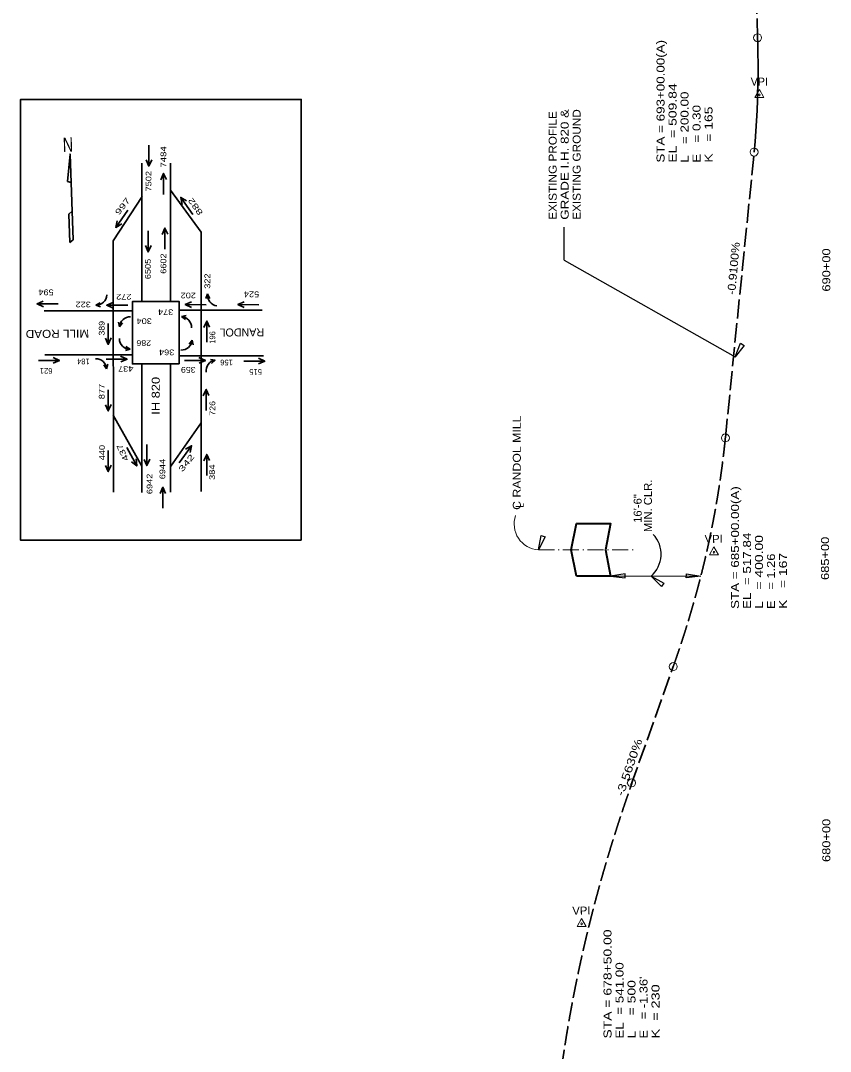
# Model space of a CAD drawing. Extents: x 2363427 to 2368559, y 6957299 to 6980140.
# Drawn here: x 2365431 to 2366849, y 6968482 to 6970286 of the extents above; entities that cross this region are included whole.
import ezdxf
from ezdxf.enums import TextEntityAlignment as Align

# ---------------------------------------------------------------- set-up
doc = ezdxf.new("R2010")
doc.units = 0
doc.header["$LTSCALE"] = 5.6
doc.linetypes.add('DOT_DASHED', pattern=[7.7, 5, -1.2, 0.3, -1.2])
doc.linetypes.add('LONG_DASHED', pattern=[7.5, 6, -1.5])
for name, color, linetype, lineweight in [('44', 7, 'Continuous', 13), ('45', 7, 'Continuous', 35), ('55', 7, 'Continuous', 35), ('61', 7, 'Continuous', 25)]:
    doc.layers.add(name, color=color, linetype=linetype, lineweight=lineweight)

msp = doc.modelspace()

# ---------------------------------------------------------------- linework, layer by layer
at = {"layer": '44'}
for p, q in [((2366724.404, 6970164.955), (2366716.366, 6970150.939)), ((2366724.404, 6970164.955), (2366732.527, 6970150.989)), ((2366716.366, 6970150.939), (2366732.527, 6970150.989)), ((2366644.717, 6969364.918), (2366636.98, 6969350.735)), ((2366636.98, 6969350.735), (2366653.136, 6969351.128)), ((2366644.717, 6969364.918), (2366653.136, 6969351.128)), ((2366413.104, 6968714.886), (2366405.367, 6968700.703)), ((2366405.367, 6968700.703), (2366421.523, 6968701.096)), ((2366413.104, 6968714.886), (2366421.523, 6968701.096))]:
    msp.add_line(p, q, dxfattribs=at)
at = {"layer": '44', "linetype": 'LONG_DASHED', "lineweight": 35}
for p, q in [((2366664.922, 6969555.558), (2366715.321, 6970055.621)), ((2366499.608, 6968947.727), (2366573.66, 6969155.558))]:
    msp.add_line(p, q, dxfattribs=at)
msp.add_lwpolyline([(2366715.321, 6970055.621), (2366716.875, 6970073.804), (2366718.23, 6970091.987), (2366719.384, 6970110.17), (2366720.339, 6970128.353), (2366721.094, 6970146.536), (2366721.396, 6970155.626), (2366721.851, 6970173.81), (2366722.105, 6970191.992), (2366722.16, 6970210.176), (2366722.014, 6970228.359), (2366721.669, 6970246.543), (2366721.421, 6970255.63), (2366697.42, 6971055.666)], dxfattribs=at)
at = {"layer": '44'}
for centre, radius in [((2366721.421, 6970255.63), 7), ((2366724.422, 6970155.625), 1.5), ((2366715.321, 6970055.621), 7), ((2366664.922, 6969555.558), 7), ((2366644.935, 6969355.59), 1.5), ((2366573.66, 6969155.558), 7), ((2366500.851, 6968952.141), 7), ((2366413.322, 6968705.558), 1.5)]:
    msp.add_circle(centre, radius, dxfattribs=at)
at = {"layer": '44', "linetype": 'LONG_DASHED', "lineweight": 35}
for points in [[(2366573.66, 6969155.558), (2366576.49, 6969163.558), (2366579.28, 6969171.558), (2366582.028, 6969179.558), (2366584.734, 6969187.558), (2366587.4, 6969195.558), (2366590.026, 6969203.558), (2366592.608, 6969211.558), (2366595.152, 6969219.558), (2366597.654, 6969227.558), (2366600.114, 6969235.558), (2366602.534, 6969243.558), (2366604.914, 6969251.558), (2366607.252, 6969259.558), (2366609.548, 6969267.558), (2366611.804, 6969275.558), (2366614.018, 6969283.558), (2366616.192, 6969291.558), (2366618.326, 6969299.558), (2366620.418, 6969307.558), (2366622.468, 6969315.558), (2366624.478, 6969323.558), (2366626.446, 6969331.558), (2366628.374, 6969339.558), (2366630.26, 6969347.558), (2366632.106, 6969355.558), (2366633.912, 6969363.558), (2366635.676, 6969371.558), (2366637.398, 6969379.558), (2366639.08, 6969387.558), (2366640.72, 6969395.558), (2366642.32, 6969403.558), (2366643.878, 6969411.558), (2366645.396, 6969419.558), (2366646.872, 6969427.558), (2366648.308, 6969435.558), (2366649.704, 6969443.558), (2366651.056, 6969451.558), (2366652.37, 6969459.558), (2366653.64, 6969467.558), (2366654.872, 6969475.558), (2366656.062, 6969483.558), (2366657.21, 6969491.558), (2366658.318, 6969499.558), (2366659.384, 6969507.558), (2366660.41, 6969515.558), (2366661.394, 6969523.558), (2366662.338, 6969531.558), (2366663.24, 6969539.558), (2366664.102, 6969547.558), (2366664.922, 6969555.558)], [(2366378.033, 6968452.021), (2366379.437, 6968462.021), (2366380.886, 6968472.021), (2366382.378, 6968482.022), (2366383.914, 6968492.022), (2366385.493, 6968502.023), (2366387.115, 6968512.023), (2366388.782, 6968522.023), (2366390.492, 6968532.024), (2366392.245, 6968542.024), (2366394.042, 6968552.025), (2366395.882, 6968562.025), (2366397.767, 6968572.026), (2366399.694, 6968582.026), (2366401.665, 6968592.027), (2366403.68, 6968602.027), (2366405.738, 6968612.028), (2366407.839, 6968622.028), (2366409.985, 6968632.029), (2366412.173, 6968642.03), (2366414.406, 6968652.03), (2366416.682, 6968662.031), (2366419.001, 6968672.031), (2366421.364, 6968682.032), (2366423.771, 6968692.033), (2366426.22, 6968702.033), (2366428.714, 6968712.034), (2366431.251, 6968722.035), (2366433.833, 6968732.035), (2366436.456, 6968742.036), (2366439.124, 6968752.037), (2366441.836, 6968762.037), (2366444.59, 6968772.038), (2366447.388, 6968782.039), (2366450.231, 6968792.04), (2366453.116, 6968802.04), (2366456.046, 6968812.041), (2366459.018, 6968822.042), (2366462.034, 6968832.043), (2366465.094, 6968842.043), (2366468.197, 6968852.044), (2366471.343, 6968862.045), (2366474.534, 6968872.046), (2366477.768, 6968882.047), (2366481.046, 6968892.048), (2366484.366, 6968902.049), (2366487.73, 6968912.049), (2366491.139, 6968922.05), (2366494.59, 6968932.051), (2366498.085, 6968942.052), (2366501.624, 6968952.053)]]:
    msp.add_spline(points, degree=3, dxfattribs=at)
at = {"layer": '45'}
msp.add_line((2365517.13, 6969897.208), (2365523.073, 6969902.238), dxfattribs=at)
for points in [[(2365523.073, 6969902.238), (2365517.838, 6970052.154), (2365513.392, 6970004.253), (2365519.583, 6970002.183)], [(2365517.13, 6969897.208), (2365515.385, 6969947.179), (2365521.328, 6969952.21)]]:
    msp.add_lwpolyline(points, dxfattribs=at)
at = {"layer": '55'}
for p, q in [((2365643.428, 6969794.124), (2365643.428, 6970035.87)), ((2365655.533, 6970031.053), (2365660.707, 6970042.25)), ((2365693.735, 6969794.124), (2365693.735, 6970035.87)), ((2365681.603, 6970018.34), (2365676.428, 6970007.144)), ((2365593.101, 6969900.17), (2365643.931, 6969978.073)), ((2365711.482, 6969976.179), (2365713.84, 6969964.072)), ((2365597.851, 6969923.779), (2365608.486, 6969930.032)), ((2365683.969, 6969922.663), (2365678.794, 6969911.467)), ((2365593.101, 6969900.17), (2365593.624, 6969460.907)), ((2365654.35, 6969881.039), (2365659.524, 6969892.236)), ((2365758.57, 6969807.362), (2365755.287, 6969799.598)), ((2365758.57, 6969807.362), (2365762.351, 6969799.405)), ((2365460.092, 6969789.861), (2365471.315, 6969784.736)), ((2365562.938, 6969787.591), (2365570.493, 6969792.125)), ((2365562.938, 6969787.591), (2365570.986, 6969785.078)), ((2365581.912, 6969787.499), (2365593.134, 6969782.374)), ((2365719.34, 6969788.908), (2365730.447, 6969783.539)), ((2365811.592, 6969788.908), (2365822.7, 6969783.539)), ((2365472.386, 6969778.042), (2365626.827, 6969778.042)), ((2365709.33, 6969779.047), (2365854.212, 6969779.047)), ((2365712.706, 6969767.821), (2365720.916, 6969769.744)), ((2365712.706, 6969767.821), (2365719.912, 6969762.751)), ((2365604.479, 6969749.622), (2365602.506, 6969757.818)), ((2365604.479, 6969749.622), (2365609.507, 6969756.857)), ((2365757.246, 6969759.972), (2365752.033, 6969748.793)), ((2365584.57, 6969719.215), (2365589.744, 6969730.411)), ((2365731.418, 6969726.786), (2365726.29, 6969719.62)), ((2365731.418, 6969726.786), (2365733.278, 6969718.564)), ((2365622.765, 6969710.643), (2365614.645, 6969708.367)), ((2365622.765, 6969710.643), (2365615.345, 6969715.398)), ((2365473.895, 6969700.643), (2365626.827, 6969700.643)), ((2365499.252, 6969690.814), (2365488.051, 6969695.987)), ((2365617.523, 6969693.176), (2365606.323, 6969698.349)), ((2365709.833, 6969699.135), (2365856.224, 6969699.135)), ((2365754.647, 6969690.942), (2365743.473, 6969696.172)), ((2365771.875, 6969691.567), (2365763.516, 6969692.675)), ((2365771.875, 6969691.567), (2365765.201, 6969685.813)), ((2365858.725, 6969689.761), (2365847.552, 6969694.991)), ((2365581.764, 6969676.243), (2365576.736, 6969683.478)), ((2365581.764, 6969676.243), (2365583.737, 6969684.439)), ((2365643.428, 6969459.902), (2365643.428, 6969685.062)), ((2365693.735, 6969460.907), (2365693.735, 6969685.062)), ((2365756.115, 6969640.355), (2365750.939, 6969629.159)), ((2365584.584, 6969602.859), (2365589.758, 6969614.055)), ((2365593.121, 6969595.098), (2365643.428, 6969506.14)), ((2365694.238, 6969506.14), (2365747.059, 6969582.032)), ((2365730.484, 6969541.819), (2365719.701, 6969535.829)), ((2365634.612, 6969506.485), (2365633.771, 6969518.791)), ((2365651.984, 6969507.197), (2365657.158, 6969518.394)), ((2365757.121, 6969526.77), (2365751.945, 6969515.574)), ((2365584.57, 6969496.568), (2365589.744, 6969507.764)), ((2365680.421, 6969469.355), (2365675.246, 6969458.158))]:
    msp.add_line(p, q, dxfattribs=at)
for points in [[(2365655.533, 6970067.766), (2365655.533, 6970031.053), (2365650.809, 6970041.862)], [(2365681.603, 6969981.628), (2365681.603, 6970018.34), (2365686.326, 6970007.533)], [(2365747.562, 6969461.912), (2365747.562, 6969915.249), (2365693.735, 6969988.928)], [(2365732.974, 6969946.409), (2365711.482, 6969976.179), (2365721.639, 6969970.178)], [(2365618.777, 6969953.949), (2365597.851, 6969923.779), (2365600.13, 6969935.352)], [(2365654.35, 6969917.752), (2365654.35, 6969881.039), (2365649.626, 6969891.848)], [(2365683.969, 6969885.95), (2365683.969, 6969922.663), (2365688.693, 6969911.856)], [(2365496.815, 6969790.02), (2365460.092, 6969789.861), (2365470.883, 6969794.63)], [(2365618.634, 6969787.658), (2365581.912, 6969787.499), (2365592.702, 6969792.268)], [(2365756.058, 6969788.262), (2365719.34, 6969788.908), (2365730.232, 6969793.44)], [(2365848.31, 6969788.262), (2365811.592, 6969788.908), (2365822.485, 6969793.44)], [(2365584.57, 6969755.928), (2365584.57, 6969719.215), (2365579.846, 6969730.023)], [(2365757.121, 6969723.259), (2365757.246, 6969759.972), (2365761.933, 6969749.147)], [(2365462.528, 6969690.814), (2365499.252, 6969690.814), (2365488.441, 6969686.091)], [(2365580.8, 6969693.176), (2365617.523, 6969693.176), (2365606.712, 6969688.454)], [(2365717.924, 6969691.129), (2365754.647, 6969690.942), (2365743.811, 6969686.274)], [(2365822.003, 6969689.948), (2365858.725, 6969689.761), (2365847.89, 6969685.093)], [(2365584.584, 6969639.571), (2365584.584, 6969602.859), (2365579.86, 6969613.666)], [(2365756.115, 6969603.643), (2365756.115, 6969640.355), (2365760.838, 6969629.548)], [(2365584.57, 6969533.281), (2365584.57, 6969496.568), (2365579.846, 6969507.375)], [(2365616.973, 6969538.686), (2365634.612, 6969506.485), (2365625.276, 6969513.697)], [(2365651.984, 6969543.91), (2365651.984, 6969507.197), (2365647.26, 6969518.005)], [(2365708.826, 6969512.172), (2365730.484, 6969541.819), (2365727.923, 6969530.306)], [(2365757.121, 6969490.058), (2365757.121, 6969526.77), (2365761.844, 6969515.962)], [(2365680.421, 6969432.642), (2365680.421, 6969469.355), (2365685.144, 6969458.547)]]:
    msp.add_lwpolyline(points, dxfattribs=at)
msp.add_lwpolyline([(2365708.826, 6969685.062), (2365708.826, 6969794.124), (2365626.827, 6969794.124), (2365626.827, 6969685.062)], close=True, dxfattribs=at)
for centre, major_axis, start_param, end_param in [((2365563.283, 6969806.366), (18.784, 0), 4.69402448, 6.24686631), ((2365777.228, 6969805.197), (-18.784, 0), 6.16762919, 7.72047102), ((2365623.241, 6969748.718), (18.784, 0), 1.54058991, 3.09343175), ((2365711.687, 6969749.071), (18.784, 0), 6.24685822, 7.79970005), ((2365622.972, 6969729.42), (-18.784, 0), 0.00689672, 1.55973855), ((2365712.669, 6969727.947), (-18.784, 0), 1.52687938, 3.07972122), ((2365563.002, 6969675.339), (-18.784, 0), 3.18975419, 4.74259602), ((2365774.729, 6969673.006), (-18.784, 0), 4.86486865, 6.41771049)]:
    msp.add_ellipse(centre, major_axis=major_axis, ratio=0.999699, start_param=start_param, end_param=end_param, dxfattribs=at)
at = {"layer": '61'}
for q in [(2366382.661, 6969924.313), (2366682.016, 6969697.181)]:
    msp.add_line((2366382.661, 6969866.347), q, dxfattribs=at)
at = {"layer": '61', "linetype": 'DOT_DASHED', "lineweight": 13}
msp.add_line((2366337.582, 6969359.74), (2366505.444, 6969359.74), dxfattribs=at)
at = {"layer": '61', "lineweight": 13}
msp.add_line((2366464.124, 6969313.738), (2366622.004, 6969313.738), dxfattribs=at)
at = {"layer": '61', "lineweight": 35}
msp.add_lwpolyline([(2365922.365, 6969376.467), (2365922.365, 6970147.616), (2365431.202, 6970147.616), (2365431.202, 6969376.467)], close=True, dxfattribs=at)
at = {"layer": '61'}
for points in [[(2366697.818, 6969717.307), (2366682.016, 6969697.181), (2366691.436, 6969721.206)], [(2366349.51, 6969382.378), (2366337.582, 6969359.74), (2366342.531, 6969385.067)], [(2366489.349, 6969318.032), (2366464.124, 6969313.738), (2366489.734, 6969310.564)], [(2366552.88, 6969295.65), (2366534.781, 6969313.738), (2366557.511, 6969301.521)], [(2366596.833, 6969318.05), (2366622.058, 6969313.756), (2366596.448, 6969310.582)]]:
    msp.add_lwpolyline(points, close=True, dxfattribs=at)
at = {"layer": '61', "lineweight": 40}
msp.add_lwpolyline([(2366404.121, 6969313.738), (2366394.921, 6969359.74), (2366404.121, 6969405.742), (2366464.124, 6969405.742), (2366454.923, 6969359.74), (2366464.124, 6969313.738)], close=True, dxfattribs=at)
at = {"layer": '61', "lineweight": 13}
msp.add_arc((2366340.722, 6969405.187), 45.556, 161.24196, 266.04749, dxfattribs=at)
at = {"layer": '61'}
msp.add_arc((2366501.724, 6969352.193), 50.71, 310.68346, 42.97044, dxfattribs=at)

# ---------------------------------------------------------------- texts
at = {"layer": '44'}
msp.add_text('VPI', height=14, rotation=0.175, dxfattribs=at).set_placement((2366724.397, 6970171.825), align=Align.CENTER)
for s, rotation, width, p in [('-0.9100%', 84.8, 1.15, (2366682.069, 6969805.61)), ('-3.5630%', 71.108, 1.3, (2366486.237, 6968927.828))]:
    msp.add_text(s, height=14, rotation=rotation, dxfattribs=dict(at, width=width)).set_placement(p)
for s, rotation, width, p in [('690+00', 90, 1.2, (2366848.607, 6969849.302)), ('VPI', 1.395, 1.05, (2366644.713, 6969371.79)), ('685+00', 90, 1.2, (2366846.378, 6969344.876)), ('680+00', 90, 1.2, (2366848.607, 6968851.488)), ('VPI', 1.395, 1.05, (2366413.1, 6968721.758))]:
    msp.add_text(s, height=14, rotation=rotation, dxfattribs=dict(at, width=width)).set_placement(p, align=Align.CENTER)
at = {"layer": '45', "width": 0.75}
msp.add_text('N', height=25, rotation=2, dxfattribs=at).set_placement((2365514.467, 6970056.139), align=Align.CENTER)
at = {"layer": '55'}
for s, height, rotation, width, p in [('7484', 10, 90, 1.25, (2365686.201, 6970047.139)), ('7502', 10, 90, 1.2, (2365660.181, 6970004.577)), ('997', 10, 52.457, 1.5, (2365613.683, 6969957.697)), ('882', 10, 125.552, 1.5, (2365741.326, 6969963.166)), ('6602', 10, 90, 1.2, (2365686.201, 6969860.508)), ('6505', 10, 90, 1.2, (2365658.999, 6969851.059)), ('322', 10, 90, 1.2, (2365763.078, 6969829.797)), ('594', 10, 180, 1.2, (2365475.762, 6969815.201)), ('272', 10, 180, 1.2, (2365611.873, 6969807.548)), ('202', 10, 180, 1.2, (2365724.765, 6969809.762)), ('524', 10, 180, 1.2, (2365835.478, 6969811.747)), ('322', 10, 180, 1.2, (2365540.809, 6969793.939)), ('374', 10, 180, 1.2, (2365685.116, 6969780.42)), ('304', 10, 180, 1.2, (2365647.602, 6969764.758)), ('MILL ROAD', 14, 180.37, 1.1, (2365495.614, 6969744.754)), ('389', 10, 90, 1.15, (2365578.155, 6969747.345)), ('286', 10, 180, 1.15, (2365646.795, 6969726.486)), ('196', 10, 90, 0.95, (2365771.936, 6969731.257)), ('364', 10, 180, 1.2, (2365686.872, 6969710.174)), ('437', 10, 180, 1.2, (2365615.24, 6969681.243)), ('359', 10, 180, 1.15, (2365724.724, 6969679.717)), ('IH 820', 14, 90, 1.2, (2365674.72, 6969629.206)), ('877', 10, 90, 1.2, (2365578.156, 6969636.629)), ('726', 10, 90, 1.15, (2365771.936, 6969607.299)), ('440', 10, 90, 1.2, (2365578.709, 6969529.866)), ('437', 10, 115.212, 1.4, (2365614.305, 6969531.885)), ('6944', 10, 90, 1.2, (2365684.415, 6969501.067)), ('342', 10, 51.023, 1.55, (2365725.374, 6969508.615)), ('6942', 10, 90, 1.2, (2365661.944, 6969475.082)), ('384', 10, 90, 1.2, (2365771.383, 6969495.556))]:
    msp.add_text(s, height=height, rotation=rotation, dxfattribs=dict(at, width=width)).set_placement(p, align=Align.CENTER)
for s, height, rotation, p in [('RANDOL', 14, 180.37, (2365818.392, 6969747.102)), ('184', 10, 180, (2365541.056, 6969694.271)), ('156', 10, 180, (2365791.757, 6969692.446)), ('621', 10, 180, (2365475.968, 6969677.733)), ('515', 10, 180, (2365842.614, 6969675.909))]:
    msp.add_text(s, height=height, rotation=rotation, dxfattribs=at).set_placement(p, align=Align.CENTER)
at = {"layer": '61'}
for s, width, p in [('STA = 693+00.00(A)', 1.25, (2366558.469, 6970037.104)), ('EL  = 509.84', 1.3, (2366579.47, 6970037.104)), ('L   = 200.00', 1.25, (2366600.471, 6970037.104)), ('EXISTING PROFILE', 1.1, (2366369.632, 6969937.142)), ('GRADE I.H. 820 & ', 1.25, (2366390.632, 6969937.142)), ('EXISTING GROUND', 1.1, (2366411.632, 6969937.142)), ('E   = 0.30', 1.25, (2366621.472, 6970037.104)), ('K   = 165', 1.3, (2366642.473, 6970037.104)), ('STA = 685+00.00(A)', 1.25, (2366688.764, 6969256.4)), ('EL  = 517.84', 1.25, (2366709.765, 6969256.4)), ('L   = 400.00', 1.3, (2366730.766, 6969256.4)), ('E   = 1.26 ', 1.2, (2366751.767, 6969256.4)), ('K   = 167', 1.3, (2366772.768, 6969256.4)), ('STA = 678+50.00', 1.3, (2366465.655, 6968504.898)), ('EL  = 541.00', 1.25, (2366486.656, 6968504.898)), ("E   = -1.36'", 1.2, (2366528.657, 6968504.898)), ('L    = 500', 1.3, (2366507.656, 6968504.898)), ('K  = 230', 1.35, (2366549.658, 6968504.898))]:
    msp.add_text(s, height=14, rotation=90, dxfattribs=dict(at, width=width)).set_placement(p)
for s, width, p in [('C RANDOL MILL', 1.15, (2366306.861, 6969512.228)), ('MIN. CLR.', 1.05, (2366536.391, 6969436.738)), ('16\'-6" ', 1.05, (2366518.39, 6969434.734)), ('L', 0.75, (2366312.11, 6969437.712))]:
    msp.add_text(s, height=14, rotation=90, dxfattribs=dict(at, width=width)).set_placement(p, align=Align.CENTER)

doc.saveas('drawing.dxf')
